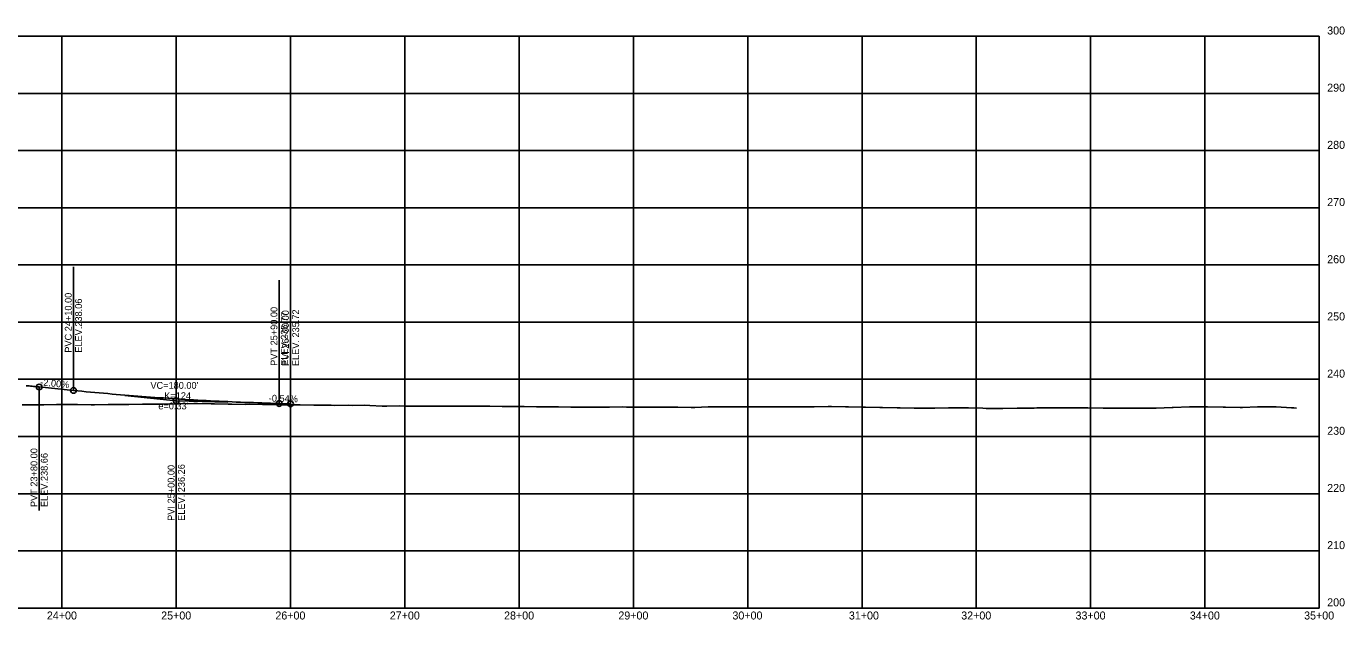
# Model space of a CAD drawing. Extents: x 976639 to 985448, y 1524031 to 1526806.
# Drawn here: x 978678 to 979832, y 1524043 to 1524562 of the extents above; entities that cross this region are included whole.
import ezdxf

# ---------------------------------------------------------------- set-up
doc = ezdxf.new("R2010")
doc.units = 0
for name, color, linetype in [('Default', 7, 'Continuous'), ('R_Axis', 7, 'Continuous'), ('R_Axis Annot', 7, 'Continuous'), ('R_Grid', 7, 'Continuous'), ('R_Vert Alg', 7, 'Continuous'), ('R_Vert Alg Annot', 7, 'Continuous')]:
    doc.layers.add(name, color=color, linetype=linetype)

msp = doc.modelspace()

# ---------------------------------------------------------------- linework, layer by layer
at = {"layer": 'Default'}
msp.add_lwpolyline([(978674.4, 1524231.3), (978678.7, 1524231.3), (978689.6, 1524231.2), (978693.4, 1524231.2), (978704.6, 1524231.5), (978708.3, 1524231.5), (978719.8, 1524231.5), (978722.9, 1524231.5), (978734.8, 1524231.2), (978737.7, 1524231.2), (978749.7, 1524231.6), (978752.9, 1524231.6), (978764.7, 1524231.4), (978767.9, 1524231.4), (978779.7, 1524231.8), (978783, 1524231.8), (978794.8, 1524231.9), (978797.8, 1524231.9), (978809.8, 1524232.2), (978812.7, 1524232.2), (978824.8, 1524232.3), (978827.8, 1524232.3), (978839.8, 1524232.2), (978842.7, 1524232.2), (978854.8, 1524231.8), (978857.8, 1524231.8), (978869.7, 1524231.6), (978873, 1524231.7), (978884.8, 1524231.5), (978887.7, 1524231.5), (978899.9, 1524231.3), (978902.7, 1524231.2), (978914.8, 1524231.2), (978917.8, 1524231.2), (978929.8, 1524231), (978932.9, 1524231), (978944.7, 1524230.8), (978947.9, 1524230.7), (978959.6, 1524230.8), (978963.1, 1524230.7), (978974.3, 1524230.8), (978978.6, 1524230.7), (978989.4, 1524230.1), (978993.5, 1524230.1), (979004.3, 1524230.2), (979008.7, 1524230.1), (979019.2, 1524230.1), (979023.9, 1524230.1), (979034.2, 1524230), (979038.8, 1524230), (979049.3, 1524230), (979053.9, 1524230), (979064.4, 1524230), (979068.7, 1524230), (979079.4, 1524230), (979083.7, 1524230), (979094.4, 1524229.8), (979098.6, 1524229.8), (979109.5, 1524229.7), (979113.6, 1524229.7), (979124.5, 1524229.4), (979128.6, 1524229.4), (979139.4, 1524229.3), (979143.6, 1524229.3), (979154.5, 1524229.2), (979158.6, 1524229.2), (979169.5, 1524229.2), (979173.5, 1524229.1), (979184.6, 1524229.2), (979188.3, 1524229.1), (979199.7, 1524229.3), (979203.2, 1524229.2), (979214.7, 1524229.1), (979218.2, 1524229.1), (979229.8, 1524229.1), (979232.9, 1524229.1), (979244.8, 1524229.1), (979248.1, 1524229.1), (979259.8, 1524229), (979263.1, 1524229), (979274.8, 1524229.4), (979278, 1524229.4), (979289.8, 1524229.4), (979293.1, 1524229.4), (979304.8, 1524229.4), (979308.1, 1524229.4), (979319.7, 1524229.3), (979323.1, 1524229.3), (979334.6, 1524229.5), (979337.9, 1524229.5), (979349.7, 1524229.5), (979352.8, 1524229.5), (979364.8, 1524229.5), (979367.5, 1524229.5), (979379.8, 1524229.6), (979382.5, 1524229.6), (979394.8, 1524229.4), (979397.5, 1524229.4), (979409.9, 1524229.2), (979412.3, 1524229.2), (979424.9, 1524228.8), (979427.3, 1524228.8), (979440, 1524228.6), (979442.6, 1524228.6), (979454.9, 1524228.4), (979458, 1524228.4), (979469.8, 1524228.4), (979473, 1524228.3), (979484.9, 1524228.6), (979487.9, 1524228.6), (979500, 1524228.6), (979502.6, 1524228.5), (979514.9, 1524228.2), (979517.8, 1524228.1), (979529.9, 1524227.9), (979532.5, 1524227.9), (979544.9, 1524228.4), (979547.3, 1524228.4), (979560, 1524228.4), (979562.2, 1524228.5), (979575, 1524228.7), (979577.1, 1524228.7), (979590.1, 1524228.6), (979592, 1524228.6), (979605.1, 1524228.7), (979606.9, 1524228.7), (979620.2, 1524228.3), (979621.9, 1524228.3), (979635.3, 1524228.2), (979637, 1524228.2), (979650.4, 1524228.4), (979651.9, 1524228.4), (979665.5, 1524228.3), (979666.7, 1524228.3), (979680.6, 1524228.9), (979681.5, 1524228.9), (979695.7, 1524229.4), (979696.3, 1524229.4), (979710.5, 1524229.5), (979711.6, 1524229.5), (979725.2, 1524229.1), (979727.3, 1524229.1), (979740.1, 1524228.9), (979742.3, 1524228.9), (979755.2, 1524229.5), (979757, 1524229.5), (979770.4, 1524229.4), (979771.7, 1524229.4), (979785.2, 1524228.5), (979787, 1524228.5), (979789.3, 1524228.4)], dxfattribs=at)
at = {"layer": 'R_Axis'}
for p, q in [((979809.3, 1524053.5), (979809.3, 1524553.5)), ((977009.3, 1524053.5), (979809.3, 1524053.5))]:
    msp.add_line(p, q, dxfattribs=at)
at = {"layer": 'R_Grid'}
for p, q in [((977009.3, 1524553.5), (979809.3, 1524553.5)), ((977009.3, 1524553.5), (979809.3, 1524553.5)), ((978709.3, 1524053.5), (978709.3, 1524553.5)), ((978809.3, 1524053.5), (978809.3, 1524553.5)), ((978909.3, 1524053.5), (978909.3, 1524553.5)), ((979009.3, 1524053.5), (979009.3, 1524553.5)), ((979109.3, 1524053.5), (979109.3, 1524553.5)), ((979209.3, 1524053.5), (979209.3, 1524553.5)), ((979309.3, 1524053.5), (979309.3, 1524553.5)), ((979409.3, 1524053.5), (979409.3, 1524553.5)), ((979509.3, 1524053.5), (979509.3, 1524553.5)), ((979609.3, 1524053.5), (979609.3, 1524553.5)), ((979709.3, 1524053.5), (979709.3, 1524553.5)), ((977009.3, 1524503.5), (979809.3, 1524503.5)), ((977009.3, 1524453.5), (979809.3, 1524453.5)), ((977009.3, 1524403.5), (979809.3, 1524403.5)), ((977009.3, 1524353.5), (979809.3, 1524353.5)), ((977009.3, 1524303.5), (979809.3, 1524303.5)), ((977009.3, 1524253.5), (979809.3, 1524253.5)), ((977009.3, 1524203.5), (979809.3, 1524203.5)), ((977009.3, 1524153.5), (979809.3, 1524153.5)), ((977009.3, 1524103.5), (979809.3, 1524103.5))]:
    msp.add_line(p, q, dxfattribs=at)
at = {"layer": 'R_Vert Alg'}
for p, q in [((978689.3, 1524246.8), (978719.3, 1524243.8)), ((978764.3, 1524239.3), (978809.3, 1524234.8)), ((978809.3, 1524234.8), (978854.3, 1524233.6)), ((978899.3, 1524232.3), (978909.3, 1524232.1))]:
    msp.add_line(p, q, dxfattribs=at)
for points in [[(978678.1, 1524247.9), (978679.3, 1524247.8), (978680.6, 1524247.7), (978681.8, 1524247.5), (978683.1, 1524247.4), (978684.3, 1524247.3), (978685.6, 1524247.2), (978686.8, 1524247), (978688.1, 1524246.9), (978689.3, 1524246.8)], [(978719.3, 1524243.8), (978723.1, 1524243.4), (978726.8, 1524243.1), (978730.6, 1524242.7), (978734.3, 1524242.3), (978738.1, 1524242), (978741.8, 1524241.6), (978745.6, 1524241.3), (978749.3, 1524241), (978753.1, 1524240.6), (978756.8, 1524240.3), (978760.6, 1524240), (978764.3, 1524239.7), (978768.1, 1524239.4), (978771.8, 1524239.1), (978775.6, 1524238.8), (978779.3, 1524238.5), (978783.1, 1524238.2), (978786.8, 1524238), (978790.6, 1524237.7), (978794.3, 1524237.4), (978798.1, 1524237.2), (978801.8, 1524236.9), (978805.6, 1524236.7), (978813.1, 1524236.2), (978816.8, 1524236), (978820.6, 1524235.7), (978824.3, 1524235.5), (978828.1, 1524235.3), (978831.8, 1524235.1), (978835.6, 1524234.9), (978839.3, 1524234.7), (978843.1, 1524234.5), (978846.8, 1524234.3), (978850.6, 1524234.2), (978854.3, 1524234), (978858.1, 1524233.8), (978861.8, 1524233.6), (978865.6, 1524233.5), (978869.3, 1524233.3), (978873.1, 1524233.2), (978876.8, 1524233.1), (978880.6, 1524232.9), (978884.3, 1524232.8), (978888.1, 1524232.7), (978891.8, 1524232.6), (978895.6, 1524232.4), (978899.3, 1524232.3)]]:
    msp.add_lwpolyline(points, dxfattribs=at)
at = {"layer": 'R_Vert Alg Annot'}
for p, q in [((978719.3, 1524273.8), (978719.3, 1524351.8)), ((978899.3, 1524262.3), (978899.3, 1524340.3)), ((978909.3, 1524262.1), (978909.3, 1524340.1)), ((978719.3, 1524243.8), (978719.3, 1524273.8)), ((978899.3, 1524232.3), (978899.3, 1524262.3)), ((978909.3, 1524232.1), (978909.3, 1524262.1)), ((978689.3, 1524246.8), (978689.3, 1524216.8)), ((978809.3, 1524234.8), (978809.3, 1524204.8)), ((978689.3, 1524216.8), (978689.3, 1524138.8)), ((978809.3, 1524204.8), (978809.3, 1524126.8))]:
    msp.add_line(p, q, dxfattribs=at)
for centre in [(978689.3, 1524246.8), (978719.3, 1524243.8), (978809.3, 1524234.8), (978899.3, 1524232.3), (978909.3, 1524232.1)]:
    msp.add_circle(centre, 2.5, dxfattribs=at)

# ---------------------------------------------------------------- texts
at = {"layer": 'R_Axis Annot'}
for s, p in [('300', (979816.3, 1524555)), ('300', (979816.3, 1524555)), ('290', (979816.3, 1524505)), ('280', (979816.3, 1524455)), ('270', (979816.3, 1524405)), ('260', (979816.3, 1524355)), ('250', (979816.3, 1524305)), ('240', (979816.3, 1524255)), ('230', (979816.3, 1524205)), ('220', (979816.3, 1524155)), ('210', (979816.3, 1524105)), ('200', (979816.3, 1524055)), ('24+00', (978696.1, 1524043.5)), ('25+00', (978796.1, 1524043.5)), ('26+00', (978896, 1524043.5)), ('27+00', (978996.1, 1524043.5)), ('28+00', (979096.1, 1524043.5)), ('29+00', (979196.1, 1524043.5)), ('30+00', (979295.9, 1524043.5)), ('31+00', (979397.8, 1524043.5)), ('32+00', (979496.1, 1524043.5)), ('33+00', (979596.1, 1524043.5)), ('34+00', (979696.1, 1524043.5)), ('35+00', (979796.1, 1524043.5))]:
    msp.add_text(s, height=7, dxfattribs=at).set_placement(p)
at = {"layer": 'R_Vert Alg Annot'}
for s, rotation, p in [('PVC 24+10.00', 90, (978717.8, 1524276.8)), ('ELEV.238.06', 90, (978726.8, 1524276.8)), ('PVT 25+90.00', 90, (978897.8, 1524265.3)), ('ELEV.235.77', 90, (978906.8, 1524265.3)), ('PVI 26+00.00', 90, (978907.8, 1524265.1)), ('ELEV. 235.72', 90, (978916.8, 1524265.1)), ('-2.00%', 354.2894, (978690.1, 1524248.2)), ('-0.54%', 358.441, (978890.2, 1524234.1)), ('PVT 23+80.00', 90, (978687.8, 1524141.8)), ('ELEV.238.66', 90, (978696.8, 1524141.8)), ('PVI 25+00.00', 90, (978807.8, 1524129.8)), ('ELEV. 236.26', 90, (978816.8, 1524129.8))]:
    msp.add_text(s, height=6, rotation=rotation, dxfattribs=at).set_placement(p)
for s, p in [("VC=180.00'", (978786.7, 1524245.2)), ('K=124', (978798.8, 1524236.2)), ("e=0.33'", (978793.6, 1524227.2))]:
    msp.add_text(s, height=6, dxfattribs=at).set_placement(p)

doc.saveas('drawing.dxf')
